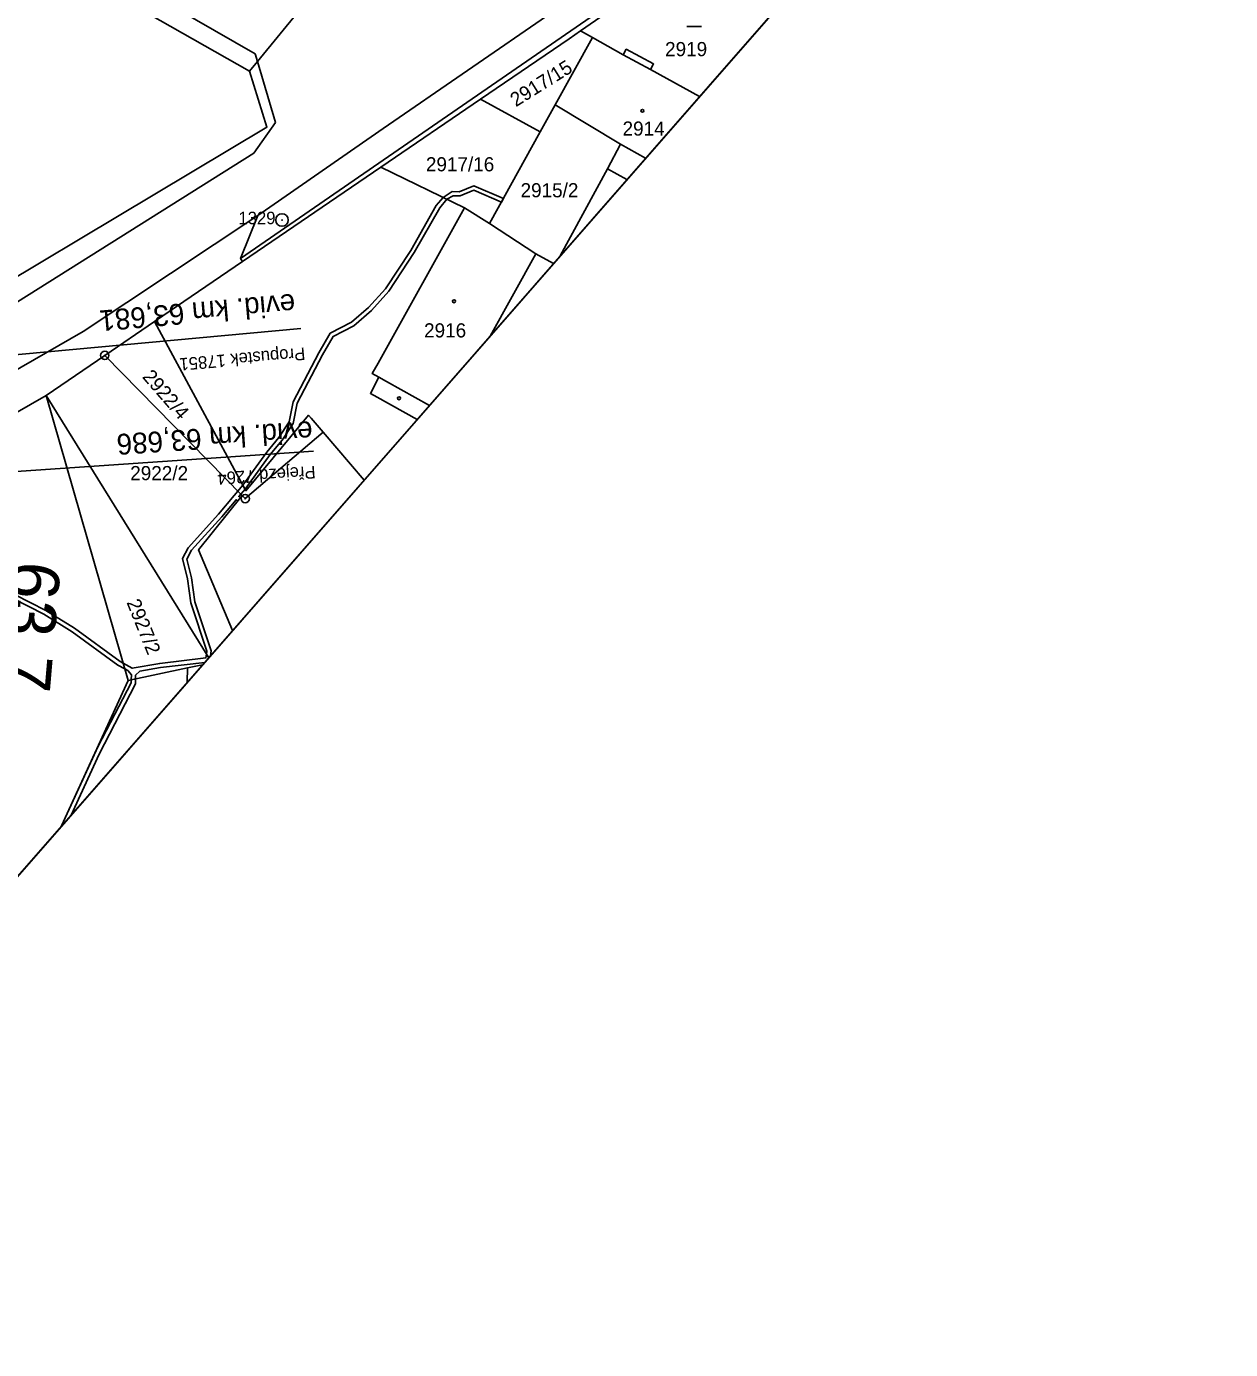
# Model space of a CAD drawing. Extents: x -620475 to -619963, y -1123010 to -1122510.
# Drawn here: x -620107.7 to -619962.9, y -1123010.1 to -1122851.2 of the extents above; entities that cross this region are included whole.
import ezdxf

# ---------------------------------------------------------------- set-up
doc = ezdxf.new("R2010")
doc.units = 0
for name, color, linetype in [('Hranice parcel', 7, 'Continuous'), ('Parcelní čísla', 7, 'Continuous'), ('Rámečky', 7, 'Continuous'), ('Rámečky-tisk', 7, 'Continuous'), ('Vnitřní kresba', 7, 'Continuous'), ('Vrstva 19', 7, 'Continuous'), ('Vrstva 4', 7, 'Continuous'), ('Vrstva 7', 7, 'Continuous'), ('Věcná břemena k části', 7, 'Continuous'), ('Značky bodu BP', 7, 'Continuous'), ('Značky budov', 7, 'Continuous'), ('Značky kultur', 7, 'Continuous')]:
    doc.layers.add(name, color=color, linetype=linetype)

msp = doc.modelspace()

# ---------------------------------------------------------------- linework, layer by layer
at = {"layer": 'Hranice parcel'}
for p, q in [((-620027.05, -1122841.96), (-620041.07, -1122851.68)), ((-620039.65, -1122852.48), (-620044.13, -1122860.59)), ((-620041.07, -1122851.68), (-620039.65, -1122852.48)), ((-620065.08, -1122868.06), (-620053.1, -1122859.89)), ((-620053.1, -1122859.89), (-620045.93, -1122863.84)), ((-620044.13, -1122860.59), (-620045.93, -1122863.84)), ((-620044.13, -1122860.59), (-620036.26, -1122865.31)), ((-620045.93, -1122863.84), (-620052.01, -1122874.84)), ((-620037.86, -1122868.27), (-620036.26, -1122865.31)), ((-620036.26, -1122865.31), (-620033.26, -1122866.98)), ((-620081.71, -1122879.39), (-620065.08, -1122868.06)), ((-620065.08, -1122868.06), (-620055.03, -1122872.95)), ((-620043.52, -1122878.71), (-620037.86, -1122868.27)), ((-620035.52, -1122869.56), (-620037.86, -1122868.27)), ((-620052.01, -1122874.84), (-620055.03, -1122872.95)), ((-620052.01, -1122874.84), (-620046.45, -1122878.47)), ((-620046.45, -1122878.47), (-620044.34, -1122879.65)), ((-620081.71, -1122879.39), (-620092.29, -1122886.6)), ((-620098.27, -1122890.68), (-620092.29, -1122886.6)), ((-620105.32, -1122895.5), (-620098.27, -1122890.68)), ((-620081.76, -1122907.52), (-620098.27, -1122890.68)), ((-620105.32, -1122895.5), (-620127.22, -1122908.12)), ((-620105.32, -1122895.5), (-620085.78, -1122927.02)), ((-620105.32, -1122895.5), (-620095.45, -1122929.76)), ((-620072.03, -1122899.92), (-620067.11, -1122905.68)), ((-620095.45, -1122929.76), (-620088.31, -1122928.24)), ((-620088.31, -1122928.24), (-620086.52, -1122927.86))]:
    msp.add_line(p, q, dxfattribs=at)
for points in [[(-619977.35, -1122803.07), (-619989.26, -1122811.36), (-619995.85, -1122815.89), (-620011.68, -1122826.8), (-620019.22, -1122832.01), (-620044.54, -1122849.47), (-620064.79, -1122863.44), (-620079.86, -1122873.87), (-620081.95, -1122879.05), (-620081.71, -1122879.39)], [(-620080.86, -1122856.55), (-620132.47, -1122827.27), (-620136.72, -1122822.9), (-620143.18, -1122816.17)], [(-620080.86, -1122856.55), (-620079.9, -1122855.37), (-620074.83, -1122849.15), (-620074.02, -1122848.16)], [(-620053.1, -1122859.89), (-620042.46, -1122852.64), (-620041.07, -1122851.68)], [(-620026.8, -1122859.59), (-620032.66, -1122856.34), (-620032.3, -1122855.67), (-620035.58, -1122853.89), (-620035.95, -1122854.57), (-620039.65, -1122852.48)], [(-620128.4, -1122892.9), (-620078.79, -1122863.28), (-620080.86, -1122856.55)], [(-620055.03, -1122872.95), (-620065.41, -1122891.61), (-620066.12, -1122892.87), (-620065.34, -1122893.31), (-620066.33, -1122895.25), (-620065.54, -1122895.69), (-620060.72, -1122898.37)], [(-620051.96, -1122888.36), (-620046.45, -1122878.47)], [(-620092.29, -1122886.6), (-620081.3, -1122906.94), (-620073.77, -1122897.87), (-620073.48, -1122898.22), (-620072.03, -1122899.92)], [(-620072.03, -1122899.92), (-620081.39, -1122907.9), (-620081.76, -1122907.52)], [(-620081.76, -1122907.52), (-620087, -1122914.03), (-620082.93, -1122923.76)], [(-620088.35, -1122929.96), (-620088.31, -1122928.24)], [(-620095.45, -1122929.76), (-620103.46, -1122947.23)]]:
    msp.add_lwpolyline(points, dxfattribs=at)
at = {"layer": 'Rámečky'}
msp.add_line((-620158.49, -1123010.14), (-619962.95, -1122786.6), dxfattribs=at)
at = {"layer": 'Rámečky-tisk'}
msp.add_lwpolyline([(-620158.49, -1123010.14), (-619962.95, -1122786.6), (-620279.07, -1122510.07)], dxfattribs=at)
at = {"layer": 'Vnitřní kresba'}
for p, q in [((-620015.73, -1122833.37), (-620081.95, -1122879.05)), ((-620104.21, -1122840.64), (-620080.18, -1122854.43)), ((-620080.18, -1122854.43), (-620079.9, -1122855.37)), ((-620035.95, -1122854.57), (-620032.66, -1122856.34)), ((-620079.9, -1122855.37), (-620077.73, -1122862.7)), ((-620077.73, -1122862.7), (-620080.37, -1122866.39)), ((-620080.37, -1122866.39), (-620119.37, -1122890.92)), ((-620100.87, -1122887.82), (-620079.86, -1122873.87)), ((-620100.87, -1122887.82), (-620115.07, -1122895.95)), ((-620065.34, -1122893.31), (-620064.4, -1122893.83)), ((-620064.4, -1122893.83), (-620059.25, -1122896.69))]:
    msp.add_line(p, q, dxfattribs=at)
at = {"layer": 'Vrstva 19'}
msp.add_line((-620074.7, -1122887.47), (-620134.45, -1122892.95), dxfattribs=at)
at = {"layer": 'Vrstva 4'}
msp.add_line((-620133.06, -1122906.27), (-620073.2, -1122902.2), dxfattribs=at)
at = {"layer": 'Věcná břemena k části'}
for p, q in [((-620086.26, -1122927.57), (-620085.78, -1122927.02)), ((-620085.78, -1122927.02), (-620085.57, -1122926.78)), ((-620103.46, -1122947.23), (-620102.31, -1122945.92))]:
    msp.add_line(p, q, dxfattribs=at)
msp.add_lwpolyline([(-620064.52, -1122882.67), (-620066.57, -1122884.95), (-620068.62, -1122886.71), (-620071.17, -1122888.03), (-620072.53, -1122890.37), (-620075.64, -1122896.27), (-620076.12, -1122898.67), (-620077.36, -1122900.56), (-620078.79, -1122902.31), (-620081.67, -1122906.26), (-620081.41, -1122906.74), (-620078.39, -1122902.61), (-620076.96, -1122900.86), (-620075.64, -1122898.87), (-620075.16, -1122896.43), (-620072.09, -1122890.61), (-620070.81, -1122888.41), (-620068.34, -1122887.13), (-620066.22, -1122885.31), (-620064.12, -1122882.97), (-620061.08, -1122878.34), (-620058.01, -1122872.96), (-620057.14, -1122871.92), (-620056.39, -1122871.51), (-620055.57, -1122871.52), (-620053.9, -1122870.84), (-620050.59, -1122872.27), (-620050.35, -1122871.83), (-620053.9, -1122870.3), (-620055.67, -1122871.02), (-620056.51, -1122871.01), (-620057.61, -1122871.7), (-620058.43, -1122872.68), (-620061.5, -1122878.08)], close=True, dxfattribs=at)
for points in [[(-620085.57, -1122926.78), (-620085.48, -1122926.2), (-620087.45, -1122920.28), (-620087.83, -1122917.42), (-620088.4, -1122915.17), (-620087.83, -1122914.07), (-620084.21, -1122910.09), (-620082.48, -1122908.04), (-620082.3, -1122908.18), (-620081.99, -1122907.79), (-620082.16, -1122907.66), (-620081.41, -1122906.74), (-620081.67, -1122906.26), (-620082.7, -1122907.53), (-620084.59, -1122909.76), (-620088.25, -1122913.79), (-620088.93, -1122915.11), (-620088.33, -1122917.52), (-620087.94, -1122920.4), (-620086, -1122926.24), (-620086.05, -1122926.58), (-620085.78, -1122927.02)], [(-620085.78, -1122927.02), (-620086.05, -1122926.58), (-620086.12, -1122927.04), (-620091.66, -1122927.7), (-620094.97, -1122928.27), (-620096.05, -1122927.68), (-620096.44, -1122927.47), (-620101.9, -1122923.47), (-620105.34, -1122921.32), (-620109.13, -1122919.41)], [(-620109.27, -1122919.9), (-620105.58, -1122921.76), (-620102.18, -1122923.89), (-620096.7, -1122927.89), (-620095.86, -1122928.36), (-620095.5, -1122928.55), (-620095.06, -1122929.07), (-620095.08, -1122929.68), (-620094.58, -1122929.57), (-620094.56, -1122929.09), (-620094.05, -1122928.61), (-620091.58, -1122928.2), (-620086.26, -1122927.57)], [(-620102.31, -1122945.92), (-620098.95, -1122938.59), (-620094.59, -1122930.17), (-620094.58, -1122929.57), (-620095.08, -1122929.68), (-620095.09, -1122930.04), (-620099.06, -1122937.63), (-620103.46, -1122947.23)]]:
    msp.add_lwpolyline(points, dxfattribs=at)
at = {"layer": 'Značky bodu BP'}
for centre, radius in [((-620076.96, -1122874.42), 0.75), ((-620076.96, -1122874.42), 0.03), ((-620098.27, -1122890.68), 0.5), ((-620098.27, -1122890.68), 0.0303), ((-620081.39, -1122907.9), 0.5), ((-620081.39, -1122907.9), 0.0303)]:
    msp.add_circle(centre, radius, dxfattribs=at)
at = {"layer": 'Značky budov'}
for centre in [(-620033.64, -1122861.3), (-620056.29, -1122884.18), (-620062.9, -1122895.84)]:
    msp.add_circle(centre, 0.175, dxfattribs=at)
at = {"layer": 'Značky kultur'}
msp.add_line((-620028.3, -1122851.16), (-620026.55, -1122851.16), dxfattribs=at)

# ---------------------------------------------------------------- texts
at = {"layer": 'Parcelní čísla'}
for s, p in [('2919', (-620030.92, -1122854.73)), ('2914', (-620036.03, -1122864.28)), ('2917/16', (-620059.67, -1122868.57)), ('2915/2', (-620048.29, -1122871.69)), ('2916', (-620059.89, -1122888.53)), ('2922/2', (-620095.21, -1122905.68))]:
    msp.add_text(s, height=1.7, dxfattribs=at).set_placement(p)
for s, rotation, p in [('2917/15', 32, (-620048.86, -1122860.88)), ('2922/4', 311, (-620093.84, -1122893.3)), ('2927/2', 292, (-620095.68, -1122920.36))]:
    msp.add_text(s, height=1.7, rotation=rotation, dxfattribs=at).set_placement(p)
at = {"layer": 'Vrstva 19'}
for s, height, p in [('evid. km 63,681', 2.5, (-620075.49, -1122883.26)), ('Propustek 17851', 1.5, (-620074.24, -1122889.72))]:
    msp.add_text(s, height=height, rotation=184.98, dxfattribs=at).set_placement(p)
at = {"layer": 'Vrstva 4'}
for s, height, p in [('evid. km 63,686', 2.5, (-620073.37, -1122898.56)), ('Přejezd 7264', 1.5, (-620072.98, -1122903.95))]:
    msp.add_text(s, height=height, rotation=183.8855, dxfattribs=at).set_placement(p)
at = {"layer": 'Vrstva 7'}
msp.add_text('63,7', height=6, rotation=265.1213, dxfattribs=at).set_placement((-620109.54, -1122915.27))
at = {"layer": 'Značky bodu BP'}
msp.add_text('1329', height=1.5, dxfattribs=at).set_placement((-620082.21, -1122874.92))

doc.saveas('drawing.dxf')
